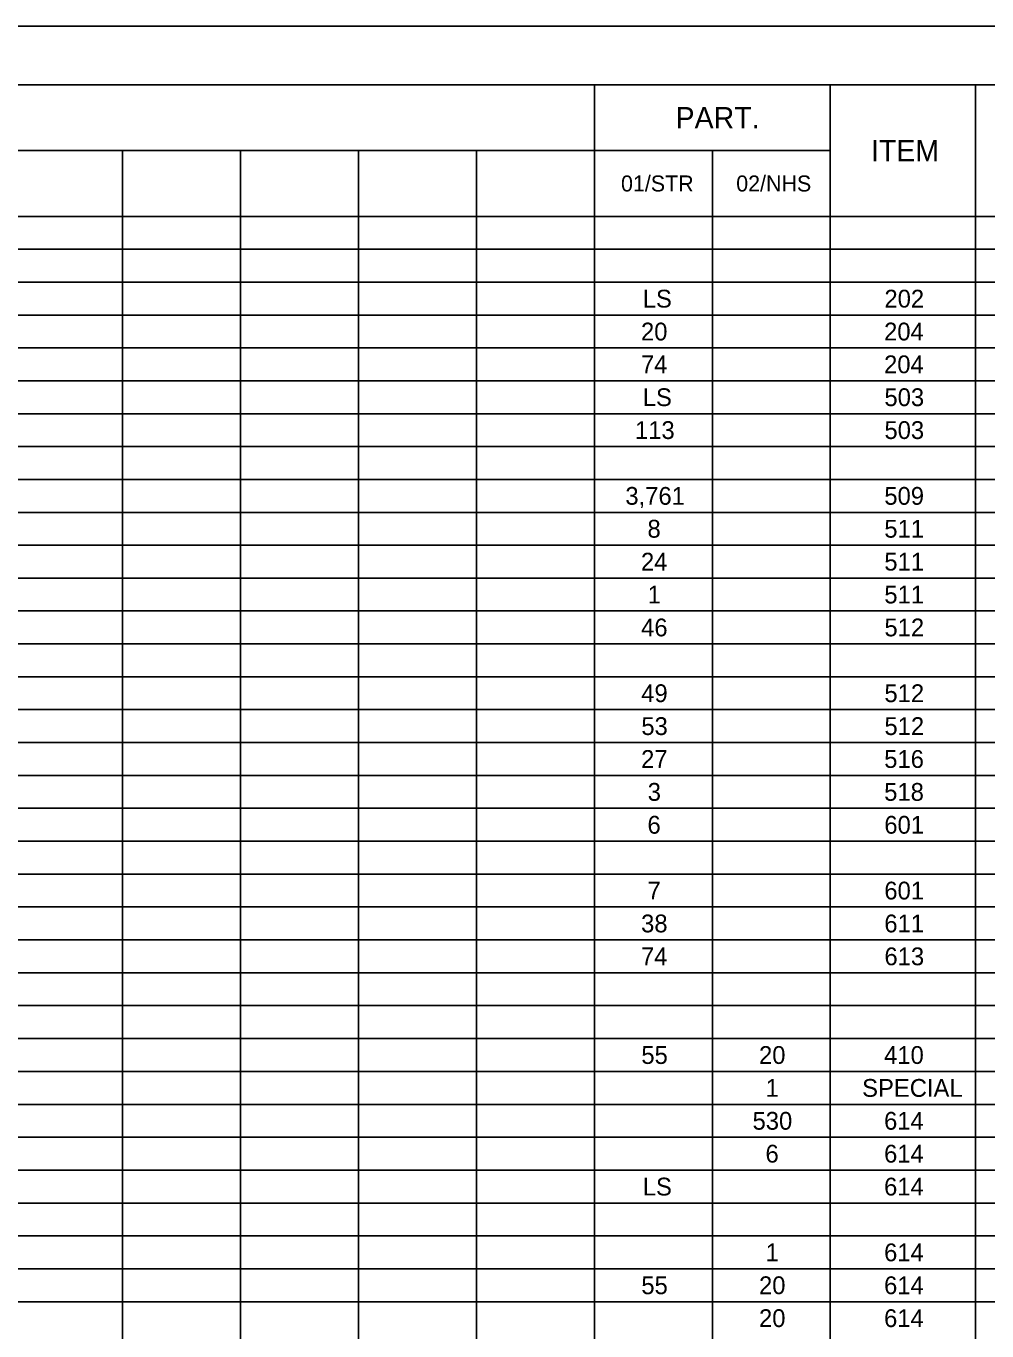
# Model space of a CAD drawing. Extents: x 0 to 34, y 0 to 22.
# Drawn here: x 8.72 to 16.9, y 10.89 to 22 of the extents above; entities that cross this region are included whole.
import ezdxf

# ---------------------------------------------------------------- set-up
doc = ezdxf.new("R2010")
doc.units = 0
for name, color, linetype in [('SH_Border', 7, 'Continuous'), ('SH_Cut_Line', 7, 'Continuous'), ('SH_Text', 7, 'Continuous')]:
    doc.layers.add(name, color=color, linetype=linetype)

msp = doc.modelspace()

# ---------------------------------------------------------------- linework, layer by layer
at = {"layer": 'SH_Border'}
msp.add_lwpolyline([(1.5, 21.5), (33.5, 21.5), (33.5, 0.5), (1.5, 0.5)], close=True, dxfattribs=at)
at = {"layer": 'SH_Cut_Line'}
msp.add_lwpolyline([(0, 0), (34, 0), (34, 22), (0, 22)], close=True, dxfattribs=at)
at = {"layer": 'SH_Text'}
for p, q in [((1.5, 21.5), (32, 21.5)), ((13.555, 21.5), (13.555, 0.502)), ((15.564, 21.5), (15.564, 0.502)), ((16.799, 21.5), (16.799, 0.502)), ((1.5, 20.94), (15.564, 20.94)), ((9.537, 20.94), (9.537, 0.502)), ((10.541, 20.94), (10.541, 0.502)), ((11.546, 20.94), (11.546, 0.502)), ((12.55, 20.94), (12.55, 0.502)), ((14.56, 20.94), (14.56, 0.502)), ((1.5, 20.38), (32, 20.38)), ((1.5, 20.1), (32, 20.1)), ((1.5, 19.82), (32, 19.82)), ((1.5, 19.54), (32, 19.54)), ((1.5, 19.26), (32, 19.26)), ((1.5, 18.98), (32, 18.98)), ((1.5, 18.7), (32, 18.7)), ((1.5, 18.42), (32, 18.42)), ((1.5, 18.14), (32, 18.14)), ((1.5, 17.86), (32, 17.86)), ((1.5, 17.58), (32, 17.58)), ((1.5, 17.3), (32, 17.3)), ((1.5, 17.021), (32, 17.021)), ((1.5, 16.741), (32, 16.741)), ((1.5, 16.461), (32, 16.461)), ((1.5, 16.181), (32, 16.181)), ((1.5, 15.901), (32, 15.901)), ((1.5, 15.621), (32, 15.621)), ((1.5, 15.341), (32, 15.341)), ((1.5, 15.061), (32, 15.061)), ((1.5, 14.781), (32, 14.781)), ((1.5, 14.501), (32, 14.501)), ((1.5, 14.221), (32, 14.221)), ((1.5, 13.941), (32, 13.941)), ((1.5, 13.661), (32, 13.661)), ((1.5, 13.381), (32, 13.381)), ((1.5, 13.101), (32, 13.101)), ((1.5, 12.821), (32, 12.821)), ((1.5, 12.541), (32, 12.541)), ((1.5, 12.261), (32, 12.261)), ((1.5, 11.981), (32, 11.981)), ((1.5, 11.701), (32, 11.701)), ((1.5, 11.421), (32, 11.421)), ((1.5, 11.141), (32, 11.141))]:
    msp.add_line(p, q, dxfattribs=at)

# ---------------------------------------------------------------- texts
for s, height, p in [('PART.', 0.1818, (14.246, 21.129)), ('ITEM', 0.1818, (15.91, 20.849)), ('01/STR', 0.1364, (13.782, 20.592)), ('02/NHS', 0.1364, (14.763, 20.592)), ('LS', 0.1515, (13.967, 19.604)), ('202', 0.1515, (16.025, 19.604)), ('20', 0.1515, (13.952, 19.324)), ('204', 0.1515, (16.022, 19.324)), ('74', 0.1515, (13.952, 19.045)), ('204', 0.1515, (16.022, 19.045)), ('LS', 0.1515, (13.967, 18.765)), ('503', 0.1515, (16.025, 18.765)), ('113', 0.1515, (13.901, 18.485)), ('503', 0.1515, (16.025, 18.485)), ('3,761', 0.1515, (13.819, 17.925)), ('509', 0.1515, (16.024, 17.925)), ('8', 0.152, (14.007, 17.645)), ('511', 0.1515, (16.024, 17.645)), ('24', 0.1515, (13.952, 17.365)), ('511', 0.1515, (16.024, 17.365)), ('1', 0.152, (14.009, 17.085)), ('511', 0.1515, (16.024, 17.085)), ('46', 0.1515, (13.953, 16.805)), ('512', 0.1515, (16.025, 16.805)), ('49', 0.1515, (13.954, 16.245)), ('512', 0.1515, (16.025, 16.245)), ('53', 0.1515, (13.955, 15.965)), ('512', 0.1515, (16.025, 15.965)), ('27', 0.1515, (13.953, 15.685)), ('516', 0.1515, (16.023, 15.685)), ('3', 0.152, (14.009, 15.405)), ('518', 0.1515, (16.023, 15.405)), ('6', 0.152, (14.007, 15.125)), ('601', 0.1515, (16.024, 15.125)), ('7', 0.152, (14.008, 14.565)), ('601', 0.1515, (16.024, 14.565)), ('38', 0.1515, (13.953, 14.285)), ('611', 0.1515, (16.024, 14.285)), ('74', 0.1515, (13.952, 14.005)), ('613', 0.1515, (16.025, 14.005)), ('55', 0.1515, (13.955, 13.165)), ('20', 0.1515, (14.957, 13.165)), ('410', 0.1515, (16.022, 13.165)), ('1', 0.152, (15.013, 12.885)), ('SPECIAL', 0.1515, (15.835, 12.885)), ('530', 0.1515, (14.902, 12.605)), ('614', 0.1515, (16.022, 12.605)), ('6', 0.152, (15.012, 12.325)), ('614', 0.1515, (16.022, 12.325)), ('LS', 0.1515, (13.967, 12.045)), ('614', 0.1515, (16.022, 12.045)), ('1', 0.152, (15.013, 11.485)), ('614', 0.1515, (16.022, 11.485)), ('55', 0.1515, (13.955, 11.205)), ('20', 0.1515, (14.957, 11.205)), ('614', 0.1515, (16.022, 11.205)), ('20', 0.1515, (14.957, 10.925)), ('614', 0.1515, (16.022, 10.925))]:
    msp.add_text(s, height=height, dxfattribs=at).set_placement(p)

doc.saveas('drawing.dxf')
